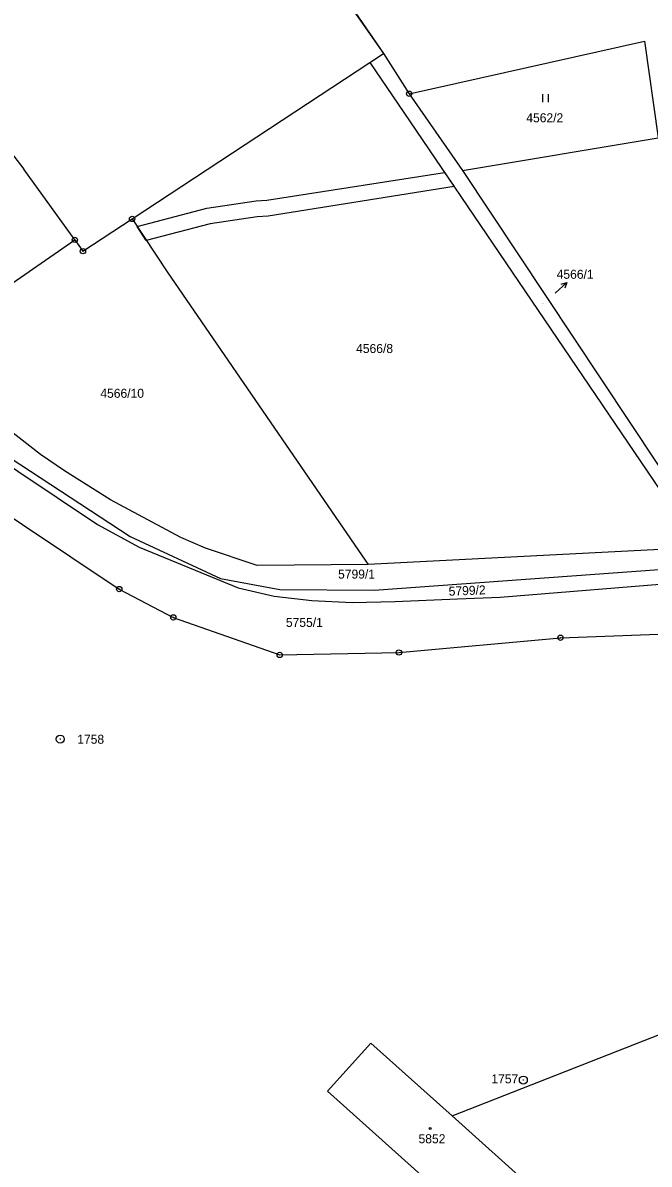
# Model space of a CAD drawing. Extents: x -735092 to -733385, y -1122435 to -1118992.
# Drawn here: x -734501.9 to -734384.1, y -1119855 to -1119640.1 of the extents above; entities that cross this region are included whole.
import ezdxf

# ---------------------------------------------------------------- set-up
doc = ezdxf.new("R2010")
doc.units = 0
for name, color, linetype in [('Vrstva 1', 7, 'Continuous'), ('Vrstva 16', 7, 'Continuous'), ('Vrstva 17', 7, 'Continuous'), ('Vrstva 18', 7, 'Continuous'), ('Vrstva 19', 7, 'Continuous'), ('Vrstva 25', 7, 'Continuous'), ('Vrstva 27', 7, 'Continuous')]:
    doc.layers.add(name, color=color, linetype=linetype)

msp = doc.modelspace()

# ---------------------------------------------------------------- linework, layer by layer
at = {"layer": 'Vrstva 1'}
for points in [[(-734484.78, -1119573.41), (-734434.03, -1119645.93)], [(-734453.89, -1119617.07), (-734434.03, -1119645.93)], [(-734429.23, -1119653.49), (-734384.91, -1119643.58)], [(-734384.91, -1119643.58), (-734382.39, -1119661.78)], [(-734436.6, -1119647.62), (-734434.03, -1119645.93)], [(-734434.03, -1119645.93), (-734429.23, -1119653.49)], [(-734481.36, -1119677.05), (-734436.6, -1119647.62)], [(-734436.6, -1119647.62), (-734429.17, -1119658.57), (-734374.77, -1119738.74), (-734374.66, -1119738.9)], [(-734513.92, -1119651.95), (-734501.72, -1119667.72)], [(-734429.23, -1119653.49), (-734419.19, -1119667.95)], [(-734419.19, -1119667.95), (-734382.39, -1119661.78)], [(-734492.14, -1119681), (-734501.72, -1119667.72)], [(-734419.19, -1119667.95), (-734372.23, -1119738.72)], [(-734490.61, -1119683.13), (-734481.36, -1119677.05)], [(-734481.36, -1119677.05), (-734474.79, -1119687.01)], [(-734519.81, -1119700.1), (-734492.14, -1119681)], [(-734492.14, -1119681), (-734490.61, -1119683.13)], [(-734474.79, -1119687.01), (-734437.38, -1119741.45)], [(-734498.58, -1119721.37), (-734504.62, -1119716.69)], [(-734510.5, -1119719.43), (-734487.9, -1119734.54)], [(-734506.11, -1119720.81), (-734481.7, -1119736.85)], [(-734494.07, -1119724.47), (-734498.58, -1119721.37)], [(-734485.4, -1119729.94), (-734494.07, -1119724.47)], [(-734511.16, -1119728.49), (-734483.78, -1119746.72)], [(-734472.18, -1119737), (-734485.4, -1119729.94)], [(-734487.9, -1119734.54), (-734480.01, -1119738.81)], [(-734481.7, -1119736.85), (-734464.75, -1119744.71)], [(-734467.55, -1119739), (-734472.18, -1119737)], [(-734480.01, -1119738.81), (-734461.39, -1119746.48)], [(-734457.83, -1119742.29), (-734467.55, -1119739)], [(-734374.66, -1119738.9), (-734436.95, -1119742.07)], [(-734437.38, -1119741.45), (-734436.95, -1119742.07)], [(-734436.95, -1119742.07), (-734457.83, -1119742.29)], [(-734435.78, -1119746.95), (-734370.05, -1119742.13)], [(-734464.75, -1119744.71), (-734453.55, -1119746.77)], [(-734412.09, -1119748.24), (-734376.67, -1119745.36)], [(-734483.78, -1119746.72), (-734473.6, -1119752.05)], [(-734461.39, -1119746.48), (-734454.64, -1119748.06)], [(-734454.64, -1119748.06), (-734447.54, -1119748.88)], [(-734453.55, -1119746.77), (-734435.78, -1119746.95)], [(-734447.54, -1119748.88), (-734439.95, -1119749.23)], [(-734439.95, -1119749.23), (-734431.85, -1119749.06)], [(-734431.85, -1119749.06), (-734420.11, -1119748.58)], [(-734420.11, -1119748.58), (-734412.09, -1119748.24)], [(-734473.6, -1119752.05), (-734453.59, -1119759.11)], [(-734431.15, -1119758.66), (-734400.74, -1119755.88)], [(-734400.74, -1119755.88), (-734375.63, -1119754.93)], [(-734453.59, -1119759.11), (-734431.15, -1119758.66)], [(-734421.15, -1119845.87), (-734378.62, -1119829.18)], [(-734444.56, -1119841.19), (-734436.42, -1119832.15)], [(-734436.42, -1119832.15), (-734421.15, -1119845.87)], [(-734444.56, -1119841.19), (-734414.31, -1119868.35)], [(-734421.15, -1119845.87), (-734406.17, -1119859.33)]]:
    msp.add_lwpolyline(points, dxfattribs=at)
at = {"layer": 'Vrstva 25'}
for points in [[(-734404.057, -1119655.085), (-734404.057, -1119653.585)], [(-734403.023, -1119655.085), (-734403.023, -1119653.585)], [(-734401.77, -1119691.05), (-734399.555, -1119689.028)], [(-734400.631, -1119689.333), (-734399.555, -1119689.028), (-734399.956, -1119690.071)]]:
    msp.add_lwpolyline(points, dxfattribs=at)
for centre, radius in [((-734429.23, -1119653.49), 0.5), ((-734429.23, -1119653.49), 0.032), ((-734481.36, -1119677.05), 0.5), ((-734481.36, -1119677.05), 0.032), ((-734492.14, -1119681), 0.5), ((-734492.14, -1119681), 0.032), ((-734490.61, -1119683.13), 0.5), ((-734490.61, -1119683.13), 0.032), ((-734483.78, -1119746.72), 0.5), ((-734483.78, -1119746.72), 0.032), ((-734473.6, -1119752.05), 0.5), ((-734473.6, -1119752.05), 0.032), ((-734400.74, -1119755.88), 0.5), ((-734400.74, -1119755.88), 0.032), ((-734453.59, -1119759.11), 0.5), ((-734431.15, -1119758.66), 0.5), ((-734431.15, -1119758.66), 0.0318), ((-734453.59, -1119759.11), 0.032), ((-734494.89, -1119774.96), 0.75), ((-734494.89, -1119774.96), 0.032), ((-734407.74, -1119839.13), 0.75), ((-734407.74, -1119839.13), 0.032), ((-734425.27, -1119848.22), 0.175)]:
    msp.add_circle(centre, radius, dxfattribs=at)
at = {"layer": 'Vrstva 27'}
msp.add_lwpolyline([(-734480.43, -1119678.46), (-734467.3, -1119675.04), (-734458.01, -1119673.66), (-734455.98, -1119673.53), (-734422.55, -1119668.32), (-734420.75, -1119670.97), (-734455.77, -1119676.53), (-734457.85, -1119676.66), (-734466.66, -1119677.96), (-734478.69, -1119681.1), (-734480.43, -1119678.46)], dxfattribs=at)

# ---------------------------------------------------------------- texts
at = {"layer": 'Vrstva 16'}
msp.add_text('4566/1', height=1.7, dxfattribs=at).set_placement((-734401.468, -1119688.32))
at = {"layer": 'Vrstva 17'}
for s, p in [('1758', (-734491.68, -1119775.83)), ('1757', (-734413.75, -1119839.74))]:
    msp.add_text(s, height=1.7, dxfattribs=at).set_placement(p)
at = {"layer": 'Vrstva 18'}
for s, height, p in [('4562/2', 1.7, (-734407.18, -1119658.87)), ('4566/1', 0.1, (-734404.234, -1119693.09)), ('4566/8', 1.7, (-734439.208, -1119702.29)), ('4566/10', 1.7, (-734487.338, -1119710.72)), ('5799/1', 1.7, (-734442.6, -1119744.75)), ('5755/1', 1.7, (-734452.42, -1119753.84))]:
    msp.add_text(s, height=height, dxfattribs=at).set_placement(p)
msp.add_text('5799/2', height=1.7, rotation=2.30002, dxfattribs=at).set_placement((-734421.749, -1119747.983))
at = {"layer": 'Vrstva 19'}
msp.add_text('5852', height=1.7, dxfattribs=at).set_placement((-734427.46, -1119851.02))

doc.saveas('drawing.dxf')
